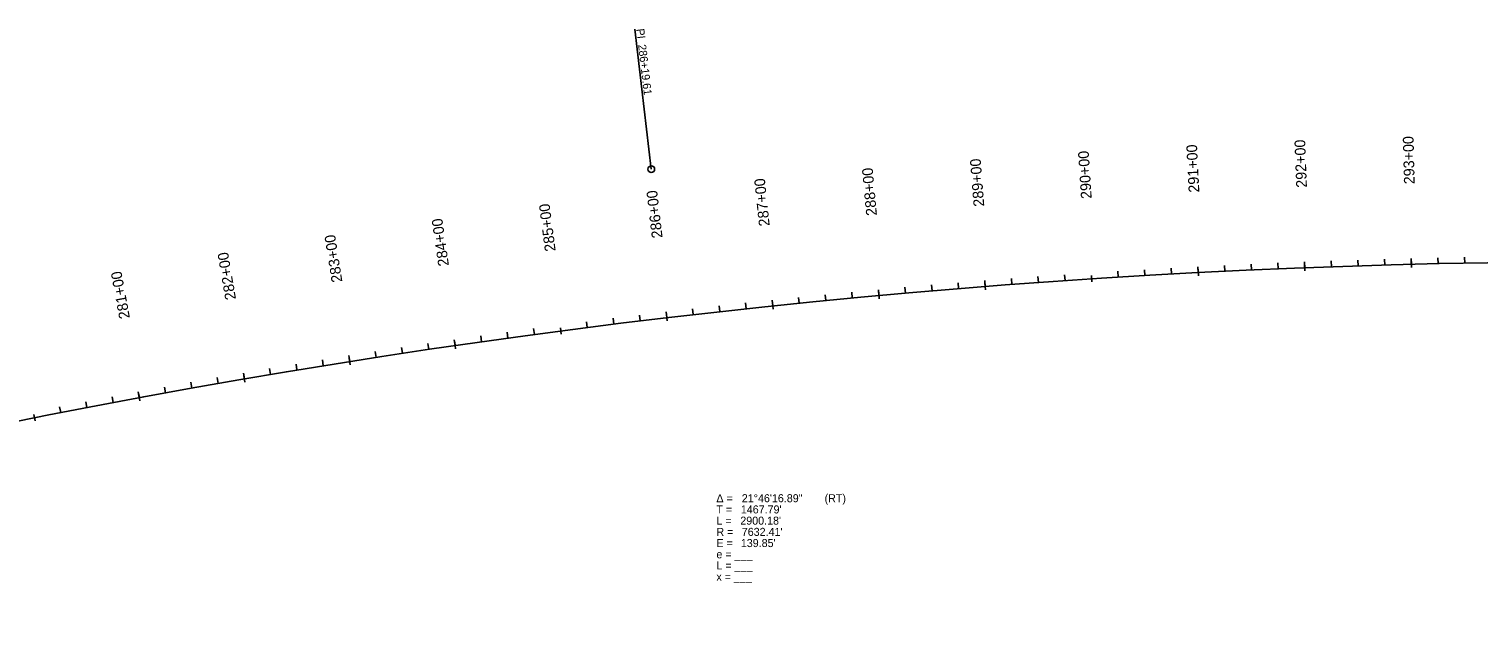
# Model space of a CAD drawing. Extents: x 20524607 to 20530050, y 8067105 to 8068411.
# Drawn here: x 20527332 to 20528690, y 8067836 to 8068411 of the extents above; entities that cross this region are included whole.
import ezdxf

# ---------------------------------------------------------------- set-up
doc = ezdxf.new("R2010")
doc.units = 0
for name, color, linetype in [('Contours Major', 7, 'Continuous'), ('Default', 7, 'Continuous'), ('Draft_DNC', 7, 'Continuous'), ('LiDAR', 7, 'Continuous'), ('Terrain', 7, 'Continuous')]:
    doc.layers.add(name, color=color, linetype=linetype)

msp = doc.modelspace()

# ---------------------------------------------------------------- linework, layer by layer
at = {"layer": 'Contours Major'}
for p, q in [((20528627.3, 8068190.5), (20528627.1, 8068196)), ((20528427.4, 8068182.8), (20528427.2, 8068188.2)), ((20528527.3, 8068187.3), (20528527.1, 8068192.7)), ((20528227.9, 8068169.8), (20528227.4, 8068175.2)), ((20528327.4, 8068180), (20528327.8, 8068173.9)), ((20528028.7, 8068151.5), (20528028.1, 8068157)), ((20528128.2, 8068161.3), (20528127.7, 8068166.7)), ((20527929.3, 8068140.5), (20527928.7, 8068145.9)), ((20527829.7, 8068131.1), (20527830.5, 8068125.1)), ((20527731, 8068114.4), (20527730.2, 8068119.8)), ((20527632.2, 8068099.5), (20527631.3, 8068104.9)), ((20527533.5, 8068083.2), (20527532.6, 8068088.6)), ((20527435, 8068065.6), (20527434, 8068071)), ((20527336.2, 8068049.8), (20527337.4, 8068043.8))]:
    msp.add_line(p, q, dxfattribs=at)
at = {"layer": 'Default'}
msp.add_arc((20528823.8, 8060560.6), 7632.4, 85.82989, 107.60125, dxfattribs=at)
at = {"layer": 'Draft_DNC'}
for p in [(20527914.9, 8068279.6), (20527899.4, 8068410.7)]:
    msp.add_line(p, (20527899.4, 8068410.7), dxfattribs=at)
msp.add_circle((20527914.9, 8068279.6), 3.12, dxfattribs=at)
at = {"layer": 'LiDAR'}
for p, q in [((20528577.3, 8068189.1), (20528577.1, 8068194.5)), ((20528602.3, 8068189.8), (20528602.1, 8068195.3)), ((20528652.3, 8068191.1), (20528652.2, 8068196.6)), ((20528677.3, 8068191.6), (20528677.2, 8068197.1)), ((20528352.6, 8068178.5), (20528352.2, 8068183.9)), ((20528377.5, 8068180), (20528377.2, 8068185.4)), ((20528402.5, 8068181.4), (20528402.2, 8068186.9)), ((20528427.3, 8068185.8), (20528427.6, 8068179.7)), ((20528452.4, 8068184), (20528452.1, 8068189.5)), ((20528477.4, 8068185.2), (20528477.1, 8068190.6)), ((20528502.4, 8068186.3), (20528502.1, 8068191.7)), ((20528527.2, 8068190.4), (20528527.5, 8068184.2)), ((20528552.3, 8068188.2), (20528552.1, 8068193.7)), ((20528627.2, 8068193.6), (20528627.4, 8068187.5)), ((20528153.1, 8068163.5), (20528152.6, 8068169)), ((20528178, 8068165.7), (20528177.6, 8068171.1)), ((20528202.9, 8068167.8), (20528202.5, 8068173.2)), ((20528227.6, 8068172.8), (20528228.1, 8068166.7)), ((20528252.8, 8068171.7), (20528252.4, 8068177.1)), ((20528277.7, 8068173.5), (20528277.3, 8068178.9)), ((20528302.7, 8068175.2), (20528302.3, 8068180.7)), ((20528327.4, 8068180), (20528327.8, 8068173.9)), ((20528003.8, 8068148.9), (20528003.3, 8068154.3)), ((20528028.4, 8068154.6), (20528029, 8068148.5)), ((20528053.6, 8068154.1), (20528053, 8068159.5)), ((20528078.5, 8068156.6), (20528077.9, 8068162)), ((20528103.3, 8068159), (20528102.8, 8068164.4)), ((20528128, 8068164.3), (20528128.5, 8068158.2)), ((20527904.5, 8068137.5), (20527903.8, 8068142.9)), ((20527929, 8068143.5), (20527929.7, 8068137.4)), ((20527954.2, 8068143.4), (20527953.5, 8068148.8)), ((20527979, 8068146.2), (20527978.4, 8068151.6)), ((20527780.5, 8068121.4), (20527779.8, 8068126.8)), ((20527805.3, 8068124.8), (20527804.6, 8068130.2)), ((20527829.7, 8068131.1), (20527830.5, 8068125.1)), ((20527854.9, 8068131.3), (20527854.2, 8068136.7)), ((20527879.7, 8068134.4), (20527879, 8068139.9)), ((20527706.3, 8068110.8), (20527705.5, 8068116.2)), ((20527730.6, 8068117.5), (20527731.5, 8068111.4)), ((20527755.8, 8068118), (20527755, 8068123.4)), ((20527607.5, 8068095.5), (20527606.6, 8068100.9)), ((20527631.7, 8068102.5), (20527632.6, 8068096.4)), ((20527656.9, 8068103.3), (20527656, 8068108.7)), ((20527681.6, 8068107.1), (20527680.8, 8068112.5)), ((20527533, 8068086.2), (20527534, 8068080.2)), ((20527558.1, 8068087.4), (20527557.2, 8068092.8)), ((20527582.8, 8068091.5), (20527581.9, 8068096.9)), ((20527459.6, 8068070.2), (20527458.7, 8068075.5)), ((20527484.2, 8068074.6), (20527483.3, 8068080)), ((20527508.9, 8068078.9), (20527507.9, 8068084.3)), ((20527385.9, 8068056.4), (20527384.9, 8068061.8)), ((20527410.5, 8068061.1), (20527409.5, 8068066.4)), ((20527434.5, 8068068.7), (20527435.6, 8068062.6)), ((20527336.2, 8068049.8), (20527337.4, 8068043.8)), ((20527361.4, 8068051.6), (20527360.3, 8068057))]:
    msp.add_line(p, q, dxfattribs=at)
at = {"layer": 'Terrain'}
msp.add_arc((20528823.8, 8060560.6), 7632.4, 85.82989, 107.60125, dxfattribs=at)

# ---------------------------------------------------------------- texts
at = {"layer": 'Contours Major'}
for s, rotation, p in [('290+00', 93.7272, (20528327.7, 8068252.1)), ('285+00', 97.4806, (20527825.3, 8068203.1))]:
    msp.add_text(s, height=10.02, rotation=rotation, dxfattribs=at).set_placement(p)
at = {"layer": 'Draft_DNC'}
for s, p in [('PI ', (20527900.8, 8068410.8)), ('286+19.61', (20527902.5, 8068396))]:
    msp.add_text(s, height=7.5, rotation=276.7156, dxfattribs=at).set_placement(p)
for s, p in [('Δ = ', (20527975.9, 8067967.6)), ('T = ', (20527975.9, 8067957.1)), ("1467.79'", (20527998.8, 8067957.1)), ('21°46\'16.89"', (20527999.7, 8067967.6)), (' (RT)', (20528074.5, 8067967.6)), ('L = ', (20527975.9, 8067946.6)), ("2900.18'", (20527998.3, 8067946.6)), ('R = ', (20527975.9, 8067936.1)), ("7632.41'", (20527999.7, 8067936.1)), ('E = ', (20527975.9, 8067925.6)), ("139.85'", (20527998.8, 8067925.6)), ('e = ___ ', (20527975.9, 8067915.1)), ('L = ___', (20527975.9, 8067904.6)), ('x = ___', (20527975.9, 8067894.1))]:
    msp.add_text(s, height=7.5, dxfattribs=at).set_placement(p)
at = {"layer": 'LiDAR'}
for s, rotation, p in [('292+00', 92.2258, (20528529.4, 8068262.4)), ('293+00', 91.4751, (20528630.4, 8068265.6)), ('290+00', 93.7272, (20528327.7, 8068252.1)), ('291+00', 92.9765, (20528428.6, 8068257.9)), ('288+00', 95.2285, (20528126.4, 8068236.4)), ('289+00', 94.4778, (20528227, 8068244.9)), ('287+00', 95.9792, (20528025.9, 8068226.6)), ('286+00', 96.7299, (20527925.5, 8068215.5)), ('285+00', 97.4806, (20527825.3, 8068203.1)), ('284+00', 98.2313, (20527725.3, 8068189.4)), ('283+00', 98.982, (20527625.4, 8068174.3)), ('282+00', 99.7327, (20527525.7, 8068158)), ('281+00', 100.4834, (20527426.3, 8068140.3))]:
    msp.add_text(s, height=10.02, rotation=rotation, dxfattribs=at).set_placement(p)

doc.saveas('drawing.dxf')
